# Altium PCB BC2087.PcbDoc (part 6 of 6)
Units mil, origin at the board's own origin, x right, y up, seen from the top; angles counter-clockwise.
Board outline 7401.57 x 1181.1 mil, 6 copper layers (Top Copper, Signal Layer 1, Signal Layer 2, Signal Layer 3, Signal Layer 4, Bottom Copper), stack 62.874 mil thick; 302 components, 237 nets, 1184 pads, 867 vias.
Unrouted connection lines stored in the file: 315.
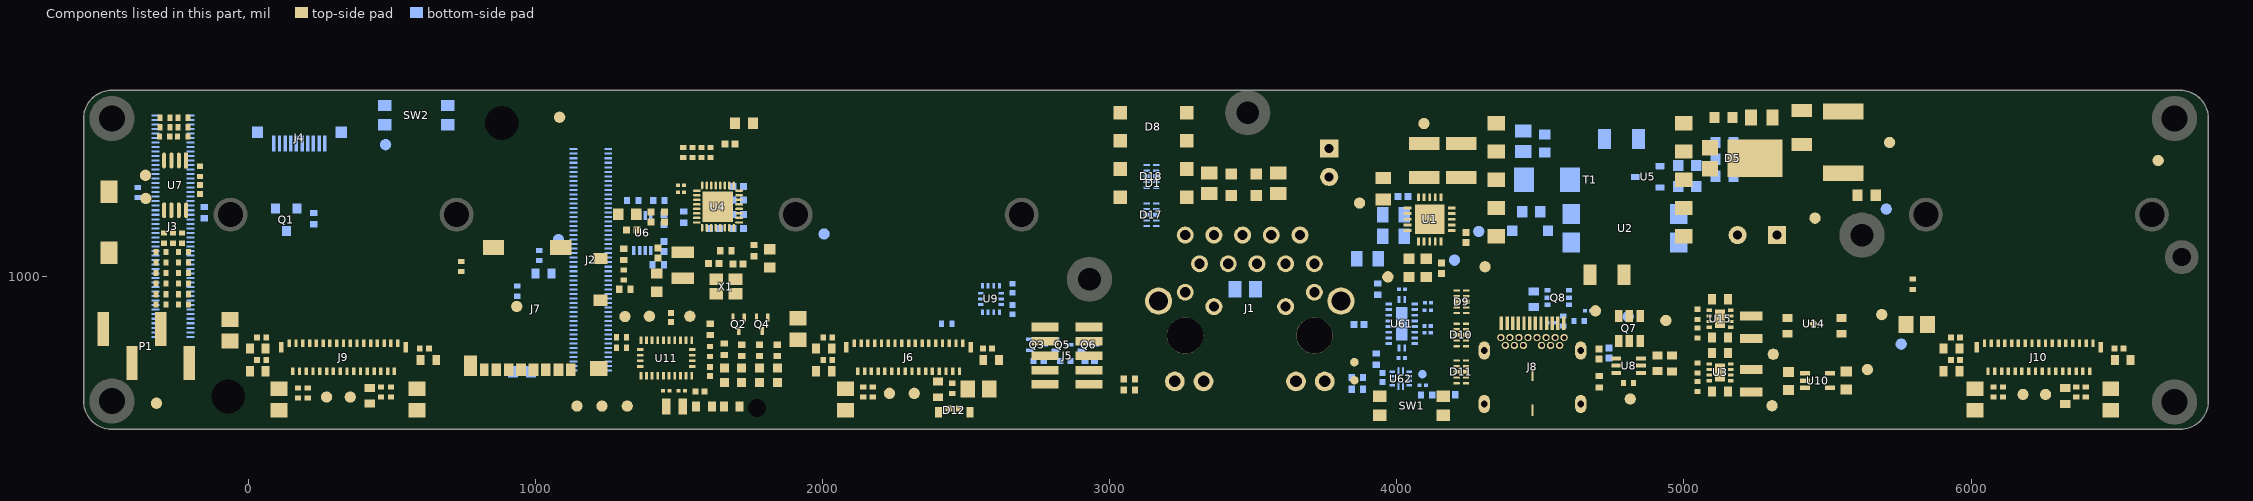
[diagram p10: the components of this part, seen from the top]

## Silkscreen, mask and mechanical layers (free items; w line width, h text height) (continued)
Drill Drawing:
  drawing of 188 lines, arcs and shapes, not listed
  text "Symbol" at 7282.54,3274.22 h72
  text "Count" at 7788.42,3274.22 h72
  text "Hole Size" at 8388.26,3274.22 h72
  text "Plated" at 9537.92,3274.22 h72
  text "Hole Type" at 10043.8,3274.22 h72
  text "Drill Layer Pair" at 10777.6,3274.22 h72
  text "Via/Pad" at 12397.11,3274.22 h72
  text "Pad Shape" at 12986.96,3274.22 h72
  text "Template" at 13732.76,3274.22 h72
  text "Hole Length" at 15082.36,3274.22 h72
  text "Routed Path Length" at 16172.04,3274.22 h72
  text "36" at 7788.42,3124.22 h60
  text "7.95mil (0.202mm)" at 8388.26,3124.22 h60
  text "PTH" at 9537.92,3124.22 h60
  text "Round" at 10043.8,3124.22 h60
  text "Top Copper - Bottom Copper" at 10777.6,3124.22 h60
  text "Via" at 12397.11,3124.22 h60
  text "Rounded" at 12986.96,3124.22 h60
  text "v41h20m0mx0(2)" at 13732.76,3124.22 h60
  text "-" at 15082.36,3124.22 h60
  text "-" at 16172.04,3124.22 h60
  text "201" at 7788.42,2974.22 h60
  text "7.99mil (0.203mm)" at 8388.26,2974.22 h60
  text "PTH" at 9537.92,2974.22 h60
  text "Round" at 10043.8,2974.22 h60
  text "Top Copper - Bottom Copper" at 10777.6,2974.22 h60
  text "Via" at 12397.11,2974.22 h60
  text "Rounded" at 12986.96,2974.22 h60
  text "v41h20m0mx0(1)" at 13732.76,2974.22 h60
  text "-" at 15082.36,2974.22 h60
  text "-" at 16172.04,2974.22 h60
  text "330" at 7788.42,2824.22 h60
  text "8.00mil (0.203mm)" at 8388.26,2824.22 h60
  text "PTH" at 9537.92,2824.22 h60
  text "Round" at 10043.8,2824.22 h60
  text "Top Copper - Bottom Copper" at 10777.6,2824.22 h60
  text "Via" at 12397.11,2824.22 h60
  text "Rounded" at 12986.96,2824.22 h60
  text "(Mixed)" at 13732.76,2824.22 h60
  text "-" at 15082.36,2824.22 h60
  text "-" at 16172.04,2824.22 h60
  text "299" at 7788.42,2674.22 h60
  text "10.00mil (0.254mm)" at 8388.26,2674.22 h60
  text "PTH" at 9537.92,2674.22 h60
  text "Round" at 10043.8,2674.22 h60
  text "Top Copper - Bottom Copper" at 10777.6,2674.22 h60
  text "Via" at 12397.11,2674.22 h60
  text "Rounded" at 12986.96,2674.22 h60
  text "(Mixed)" at 13732.76,2674.22 h60
  text "-" at 15082.36,2674.22 h60
  text "-" at 16172.04,2674.22 h60
  text "1" at 7788.42,2524.22 h60
  text "11.81mil (0.300mm)" at 8388.26,2524.22 h60
  text "PTH" at 9537.92,2524.22 h60
  text "Round" at 10043.8,2524.22 h60
  text "Top Copper - Bottom Copper" at 10777.6,2524.22 h60
  text "Via" at 12397.11,2524.22 h60
  text "Rounded" at 12986.96,2524.22 h60
  text "v50h30m0mx0" at 13732.76,2524.22 h60
  text "-" at 15082.36,2524.22 h60
  text "-" at 16172.04,2524.22 h60
  text "14" at 7788.42,2374.22 h60
  text "15.75mil (0.400mm)" at 8388.26,2374.22 h60
  text "PTH" at 9537.92,2374.22 h60
  text "Round" at 10043.8,2374.22 h60
  text "Top Copper - Bottom Copper" at 10777.6,2374.22 h60
  text "Pad" at 12397.11,2374.22 h60
  text "Rounded" at 12986.96,2374.22 h60
  text "c65h40" at 13732.76,2374.22 h60
  text "-" at 15082.36,2374.22 h60
  text "-" at 16172.04,2374.22 h60
  text "4" at 7788.42,2224.22 h60
  text "23.62mil (0.600mm)" at 8388.26,2224.22 h60
  text "PTH" at 9537.92,2224.22 h60
  text "Slot" at 10043.8,2224.22 h60
  text "Top Copper - Bottom Copper" at 10777.6,2224.22 h60
  text "Pad" at 12397.11,2224.22 h60
  text "Rounded" at 12986.96,2224.22 h60
  text "r100_160h60_120r100" at 13732.76,2224.22 h60
  text "47.24mil (1.200mm)" at 15082.36,2224.22 h60
  text "23.62mil (0.600mm)" at 16172.04,2224.22 h60
  text "4" at 7788.42,2074.22 h60
  text "31.50mil (0.800mm)" at 8388.26,2074.22 h60
  text "PTH" at 9537.92,2074.22 h60
  text "Round" at 10043.8,2074.22 h60
  text "Top Copper - Bottom Copper" at 10777.6,2074.22 h60
  text "Pad" at 12397.11,2074.22 h60
  text "Rounded" at 12986.96,2074.22 h60
  text "(Mixed)" at 13732.76,2074.22 h60
  text "-" at 15082.36,2074.22 h60
  text "-" at 16172.04,2074.22 h60
  text "14" at 7788.42,1924.22 h60
  text "35.43mil (0.900mm)" at 8388.26,1924.22 h60
  text "PTH" at 9537.92,1924.22 h60
  text "Round" at 10043.8,1924.22 h60
  text "Top Copper - Bottom Copper" at 10777.6,1924.22 h60
  text "Pad" at 12397.11,1924.22 h60
  text "Rounded" at 12986.96,1924.22 h60
  text "c150h90" at 13732.76,1924.22 h60
  text "-" at 15082.36,1924.22 h60
  text "-" at 16172.04,1924.22 h60
  text "4" at 7788.42,1774.22 h60
  text "40.16mil (1.020mm)" at 8388.26,1774.22 h60
  text "PTH" at 9537.92,1774.22 h60
  text "Round" at 10043.8,1774.22 h60
  text "Top Copper - Bottom Copper" at 10777.6,1774.22 h60
  text "Pad" at 12397.11,1774.22 h60
  text "Rounded" at 12986.96,1774.22 h60
  text "c175h102" at 13732.76,1774.22 h60
  text "-" at 15082.36,1774.22 h60
  text "-" at 16172.04,1774.22 h60
  text "2" at 7788.42,1624.22 h60
  text "62.99mil (1.600mm)" at 8388.26,1624.22 h60
  text "(Mixed)" at 9537.92,1624.22 h60
  text "Round" at 10043.8,1624.22 h60
  text "Top Copper - Bottom Copper" at 10777.6,1624.22 h60
  text "Pad" at 12397.11,1624.22 h60
  text "Rounded" at 12986.96,1624.22 h60
  text "(Mixed)" at 13732.76,1624.22 h60
  text "-" at 15082.36,1624.22 h60
  text "-" at 16172.04,1624.22 h60
  text "2" at 7788.42,1474.22 h60
  text "66.93mil (1.700mm)" at 8388.26,1474.22 h60
  text "PTH" at 9537.92,1474.22 h60
  text "Round" at 10043.8,1474.22 h60
  text "Top Copper - Bottom Copper" at 10777.6,1474.22 h60
  text "Pad" at 12397.11,1474.22 h60
  text "Rounded" at 12986.96,1474.22 h60
  text "c240h170" at 13732.76,1474.22 h60
  text "-" at 15082.36,1474.22 h60
  text "-" at 16172.04,1474.22 h60
  text "3" at 7788.42,1324.22 h60
  text "78.74mil (2.000mm)" at 8388.26,1324.22 h60
  text "PTH" at 9537.92,1324.22 h60
  text "Round" at 10043.8,1324.22 h60
  text "Top Copper - Bottom Copper" at 10777.6,1324.22 h60
  text "Pad" at 12397.11,1324.22 h60
  text "Rounded" at 12986.96,1324.22 h60
  text "c400h200z250" at 13732.76,1324.22 h60
  text "-" at 15082.36,1324.22 h60
  text "-" at 16172.04,1324.22 h60
  text "6" at 7788.42,1174.22 h60
  text "86.61mil (2.200mm)" at 8388.26,1174.22 h60
  text "PTH" at 9537.92,1174.22 h60
  text "Round" at 10043.8,1174.22 h60
  text "Top Copper - Bottom Copper" at 10777.6,1174.22 h60
  text "Pad" at 12397.11,1174.22 h60
  text "Rounded" at 12986.96,1174.22 h60
  text "c300h220" at 13732.76,1174.22 h60
  text "-" at 15082.36,1174.22 h60
  text "-" at 16172.04,1174.22 h60
  text "A" at 7253.45,1164.23 h66.67
  text "4" at 7788.42,1024.22 h60
  text "90.55mil (2.300mm)" at 8388.26,1024.22 h60
  text "PTH" at 9537.92,1024.22 h60
  text "Round" at 10043.8,1024.22 h60
  text "Top Copper - Bottom Copper" at 10777.6,1024.22 h60
  text "Pad" at 12397.11,1024.22 h60
  text "Rounded" at 12986.96,1024.22 h60
  text "c400h230z250" at 13732.76,1024.22 h60
  text "-" at 15082.36,1024.22 h60
  text "-" at 16172.04,1024.22 h60
  text "B" at 7253.45,1014.23 h66.67
  text "2" at 7788.42,874.22 h60
  text "118.11mil (3.000mm)" at 8388.26,874.22 h60
  text "PTH" at 9537.92,874.22 h60
  text "Round" at 10043.8,874.22 h60
  text "Top Copper - Bottom Copper" at 10777.6,874.22 h60
  text "Pad" at 12397.11,874.22 h60
  text "Rounded" at 12986.96,874.22 h60
  text "c270h300x530m275mx535" at 13732.76,874.22 h60
  text "-" at 15082.36,874.22 h60
  text "-" at 16172.04,874.22 h60
  text "2" at 7788.42,724.22 h60
  text "125.98mil (3.200mm)" at 8388.26,724.22 h60
  text "PTH" at 9537.92,724.22 h60
  text "Round" at 10043.8,724.22 h60
  text "Top Copper - Bottom Copper" at 10777.6,724.22 h60
  text "Pad" at 12397.11,724.22 h60
  text "Rounded" at 12986.96,724.22 h60
  text "c320h320(Tol0-0)" at 13732.76,724.22 h60
  text "-" at 15082.36,724.22 h60
  text "-" at 16172.04,724.22 h60
  text "928 Total" at 7788.42,574.22 h60
  text "Slot definitions :" at 7282.54,429.24 h60
  text "Routed Path Length" at 8315.23,429.24 h60
  text "= Calculated from tool start centre position to tool end centre position." at 9417.9,429.24 h60
  text "Hole Length" at 8315.23,329.27 h60
  text "= Routed Path Length + Tool Size = Slot length as defined in the PCB layout" at 9008.03,329.27 h60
